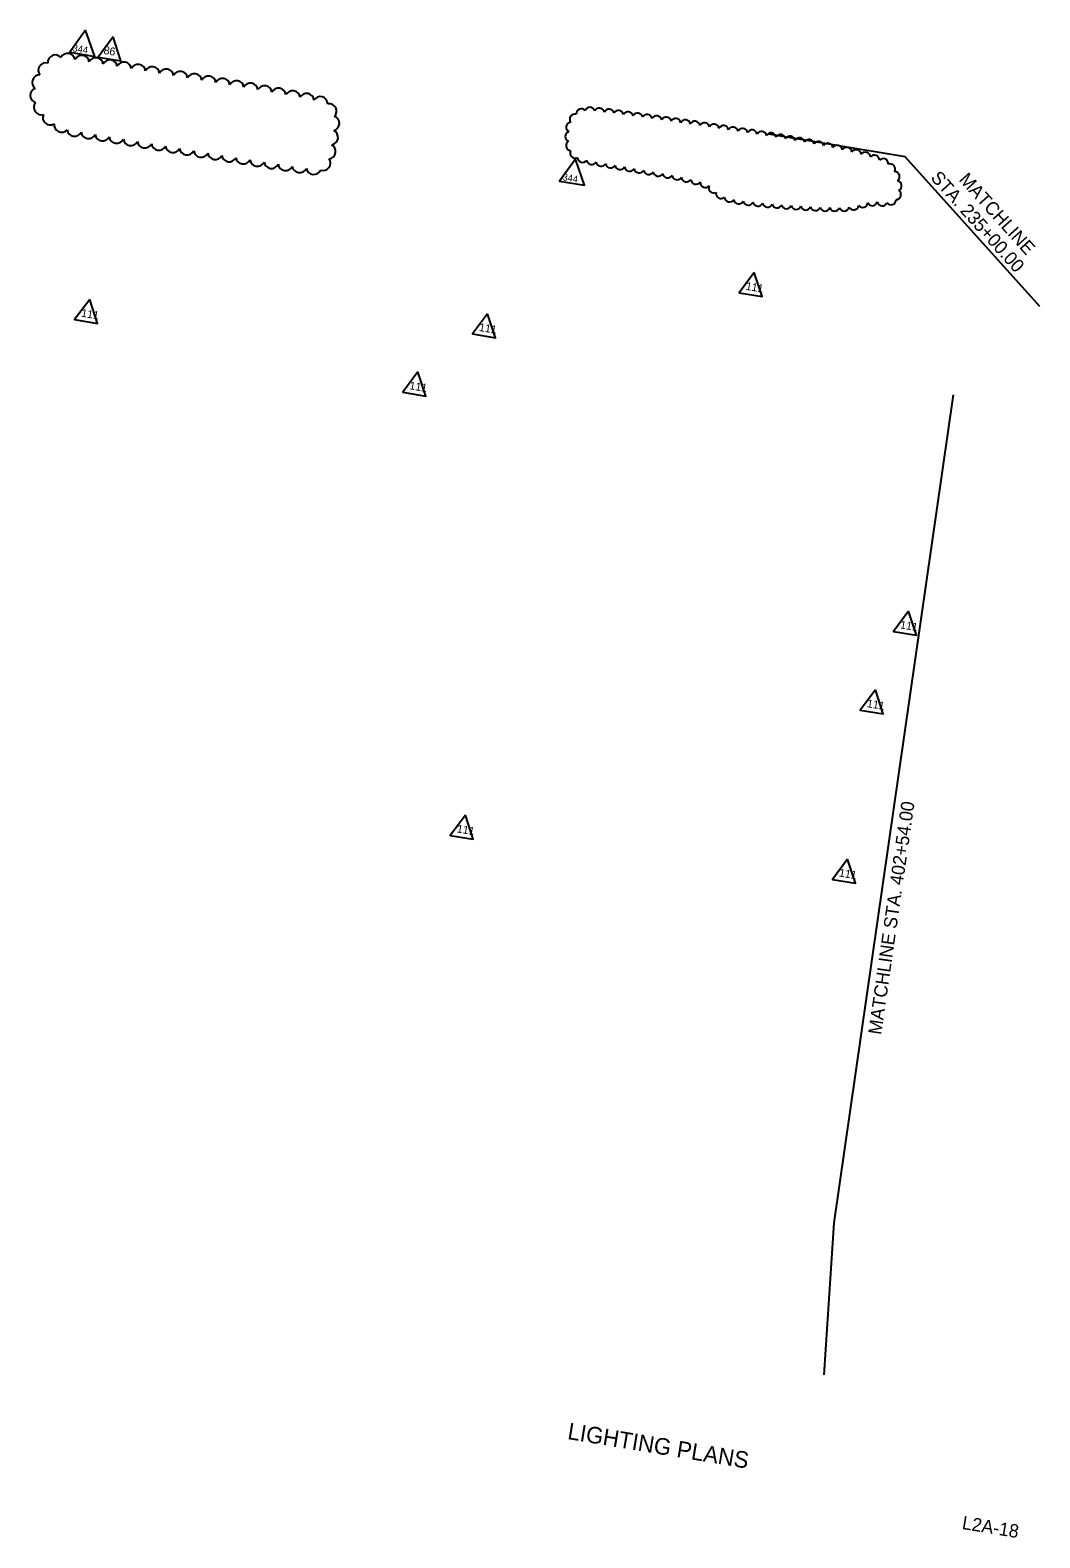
# Model space of a CAD drawing. Extents: x 927483 to 928746, y 636242 to 637203.
# Drawn here: x 928134 to 928746, y 636242 to 637154 of the extents above; entities that cross this region are included whole.
import ezdxf

# ---------------------------------------------------------------- set-up
doc = ezdxf.new("R2010")
doc.units = 0
for name, color, linetype in [('Cloud_dp', 7, 'Continuous'), ('PlotBorder_dp', 7, 'Continuous'), ('TextMisc', 7, 'Continuous'), ('TextShtNo', 7, 'Continuous')]:
    doc.layers.add(name, color=color, linetype=linetype)

msp = doc.modelspace()

# ---------------------------------------------------------------- linework, layer by layer
at = {"layer": 'Cloud_dp'}
for points in [[(928168.06, 637154.17), (928158.42, 637140.83), (928173.54, 637138.32)], [(928184.68, 637150.12), (928175.53, 637137.88), (928189.42, 637135.59)], [(928464.59, 637076.11), (928454.96, 637062.76), (928470.08, 637060.26)], [(928572.74, 637007.49), (928563.59, 636995.25), (928577.49, 636992.96)], [(928170.49, 636991.25), (928161.34, 636979.01), (928175.23, 636976.72)], [(928411.3, 636982.56), (928402.15, 636970.32), (928416.04, 636968.03)], [(928369.2, 636947.28), (928360.04, 636935.05), (928373.94, 636932.75)], [(928666.19, 636802.56), (928657.04, 636790.32), (928670.93, 636788.03)], [(928646.1, 636754.9), (928636.94, 636742.66), (928650.84, 636740.37)], [(928397.88, 636679.08), (928388.73, 636666.84), (928402.63, 636664.55)], [(928629.2, 636652.42), (928620.05, 636640.18), (928633.94, 636637.89)]]:
    msp.add_lwpolyline(points, close=True, dxfattribs=at)
for centre, radius, start, end in [((928143.89, 637129.9), 4.52, 73.90987, 218.90987), ((928149.65, 637134.66), 4.52, 40.26243, 185.26243), ((928157.18, 637135.62), 4.52, 9.30458, 154.30458), ((928165.7, 637134.35), 4.52, 8.73218, 153.73218), ((928174.22, 637133.02), 4.52, 8.52219, 153.52219), ((928182.74, 637131.66), 4.52, 8.40298, 153.40298), ((928191.26, 637130.29), 4.52, 8.32347, 153.32347), ((928199.77, 637128.91), 4.52, 8.26555, 153.26555), ((928140.25, 637122.53), 4.52, 88.47694, 233.47694), ((928208.29, 637127.52), 4.52, 8.22093, 153.22093), ((928216.8, 637126.13), 4.52, 8.18518, 153.18518), ((928225.32, 637124.73), 4.52, 8.15571, 153.15571), ((928233.83, 637123.33), 4.52, 8.11336, 153.11336), ((928242.34, 637121.92), 4.52, 8.03146, 153.03146), ((928250.85, 637120.49), 4.52, 7.9329, 152.9329), ((928259.35, 637119.05), 4.52, 7.81266, 152.81266), ((928138.99, 637114.6), 4.52, 108.37643, 253.37643), ((928267.85, 637117.58), 4.52, 7.6614, 152.6614), ((928276.35, 637116.1), 4.52, 7.46294, 152.46294), ((928284.83, 637114.57), 4.52, 7.18599, 152.18599), ((928293.31, 637113), 4.52, 6.75925, 151.75925), ((928301.75, 637111.33), 4.52, 5.9631, 150.9631), ((928141.21, 637107.42), 4.52, 141.03927, 286.03927), ((928310.1, 637109.41), 4.53, 3.089, 148.089), ((928315.41, 637105.2), 4.52, 315.06597, 100.06597), ((928468.08, 637103.53), 3.06, 40.63294, 185.63294), ((928473.28, 637104.46), 3.06, 14.7979, 159.7979), ((928479.03, 637104), 3.06, 11.05429, 156.05429), ((928484.81, 637103.31), 3.06, 10.33145, 155.33145), ((928490.6, 637102.57), 3.06, 9.95906, 154.95906), ((928146.62, 637101.29), 4.52, 156.76094, 301.76094), ((928153.48, 637096.85), 4.52, 172.43776, 317.43776), ((928317.11, 637097.74), 4.52, 285.69264, 70.69264), ((928461.97, 637095.41), 3.06, 95.38603, 240.38603), ((928464.11, 637100.31), 3.06, 72.42003, 217.42003), ((928496.38, 637101.79), 3.06, 9.72161, 154.72161), ((928502.16, 637100.99), 3.06, 9.55316, 154.55316), ((928507.93, 637100.18), 3.06, 9.42562, 154.42562), ((928513.71, 637099.35), 3.06, 9.32472, 154.32472), ((928519.48, 637098.52), 3.06, 9.24229, 154.24229), ((928525.26, 637097.68), 3.06, 9.17332, 154.17332), ((928531.03, 637096.83), 3.06, 9.11448, 154.11448), ((928536.8, 637095.98), 3.06, 9.06353, 154.06353), ((928542.57, 637095.12), 3.06, 9.01883, 154.01883), ((928548.35, 637094.26), 3.06, 8.97922, 153.97922), ((928554.12, 637093.39), 3.06, 8.94378, 153.94378), ((928161.29, 637094.43), 4.52, 188.13813, 333.13813), ((928169.81, 637093.03), 4.52, 188.13813, 333.13813), ((928178.32, 637091.62), 4.52, 188.13813, 333.13813), ((928186.83, 637090.22), 4.52, 188.13813, 333.13813), ((928195.35, 637088.82), 4.52, 188.13813, 333.13813), ((928316.33, 637089.33), 4.52, 278.78201, 63.78201), ((928461.35, 637089.82), 3.06, 106.81284, 251.81284), ((928559.89, 637092.52), 3.06, 8.91184, 153.91184), ((928565.66, 637091.65), 3.06, 8.83856, 153.83856), ((928571.42, 637090.76), 3.06, 8.65118, 153.65118), ((928577.18, 637089.85), 3.06, 8.4393, 153.4393), ((928582.94, 637088.92), 3.06, 8.20357, 153.20357), ((928588.69, 637087.96), 3.06, 7.93917, 152.93917), ((928594.44, 637086.98), 3.06, 7.63978, 152.63978), ((928600.18, 637085.96), 3.06, 7.29698, 152.29698), ((928605.92, 637084.91), 3.06, 6.89918, 151.89918), ((928203.86, 637087.41), 4.52, 188.13813, 333.13813), ((928212.37, 637086.01), 4.52, 188.13813, 333.13813), ((928220.89, 637084.6), 4.52, 188.13813, 333.13813), ((928229.4, 637083.2), 4.52, 188.13813, 333.13813), ((928237.92, 637081.8), 4.52, 188.15136, 333.15136), ((928246.43, 637080.4), 4.52, 188.21878, 333.21878), ((928254.94, 637079.02), 4.52, 188.30566, 333.30566), ((928314.89, 637080.87), 4.52, 276.84023, 61.84023), ((928461.9, 637084.25), 3.06, 119.56995, 264.56995), ((928464.31, 637079.77), 3.06, 151.98053, 296.98053), ((928611.64, 637083.82), 3.06, 6.42994, 151.42994), ((928617.35, 637082.67), 3.06, 5.86508, 150.86508), ((928623.05, 637081.46), 3.06, 5.16711, 150.16711), ((928628.73, 637080.17), 3.06, 4.27426, 149.27426), ((928634.38, 637078.78), 3.06, 3.07552, 148.07552), ((928639.98, 637077.25), 3.06, 1.34531, 146.34531), ((928645.5, 637075.5), 3.06, 358.52699, 143.52699), ((928263.46, 637077.65), 4.52, 188.41403, 333.41403), ((928271.98, 637076.3), 4.52, 188.55453, 333.55453), ((928280.5, 637074.97), 4.52, 188.74713, 333.74713), ((928289.03, 637073.68), 4.52, 189.03514, 334.03514), ((928297.55, 637072.45), 4.52, 189.53975, 334.53975), ((928306.08, 637071.36), 4.52, 190.88635, 335.88635), ((928311.74, 637073.77), 4.52, 250.27296, 35.27296), ((928468.76, 637077.2), 3.06, 182.93135, 327.93135), ((928474.39, 637075.91), 3.06, 186.32628, 331.32628), ((928480.11, 637074.82), 3.06, 187.09289, 332.09289), ((928485.85, 637073.79), 3.06, 187.49423, 332.49423), ((928491.59, 637072.79), 3.06, 187.75195, 332.75195), ((928497.34, 637071.81), 3.06, 187.93551, 332.93551), ((928503.1, 637070.85), 3.06, 188.07485, 333.07485), ((928508.85, 637069.88), 3.06, 187.92729, 332.92729), ((928650.82, 637073.36), 3.06, 352.63382, 137.63382), ((928655.04, 637070.15), 3.06, 327.95541, 112.95541), ((928514.61, 637068.88), 3.06, 187.39782, 332.39782), ((928520.36, 637067.82), 3.06, 186.70849, 331.70849), ((928526.1, 637066.68), 3.06, 185.75933, 330.75933), ((928531.82, 637065.42), 3.06, 184.33108, 329.33108), ((928537.51, 637063.95), 3.06, 181.80541, 326.80541), ((928543.12, 637062.01), 3.06, 175.00091, 320.00091), ((928548.19, 637058.65), 3.06, 152.86429, 297.86429), ((928657.66, 637065.47), 3.06, 305.50897, 90.50897), ((928658.91, 637059.97), 3.06, 294.95743, 79.95743), ((928552.61, 637055.32), 3.06, 168.26885, 313.26885), ((928557.77, 637053.23), 3.06, 182.59517, 327.59517), ((928563.37, 637052.07), 3.06, 188.97993, 333.97993), ((928569.13, 637051.3), 3.06, 190.78991, 335.78991), ((928655.51, 637051.51), 3.06, 216.51399, 1.51399), ((928658.5, 637054.65), 3.06, 271.24021, 56.24021), ((928574.91, 637050.67), 3.06, 191.72761, 336.72761), ((928580.71, 637050.11), 3.06, 192.32661, 337.32661), ((928586.52, 637049.61), 3.06, 192.75186, 337.75186), ((928592.33, 637049.14), 3.06, 193.07393, 338.07393), ((928598.15, 637048.71), 3.06, 193.3964, 338.3964), ((928603.96, 637048.32), 3.06, 193.9412, 338.9412), ((928609.78, 637047.99), 3.06, 194.66476, 339.66476), ((928615.59, 637047.76), 3.06, 195.66832, 340.66832), ((928621.4, 637047.65), 3.06, 197.19682, 342.19682), ((928627.19, 637047.76), 3.06, 199.96678, 344.96678), ((928632.84, 637048.41), 3.06, 208.14735, 353.14735), ((928638.35, 637049.86), 3.06, 216.33537, 1.33537), ((928644.28, 637050.98), 3.06, 200.14494, 345.14494), ((928650.22, 637050.86), 3.06, 192.51704, 337.51704)]:
    msp.add_arc(centre, radius, start, end, dxfattribs=at)
at = {"layer": 'PlotBorder_dp'}
for p, q in [((928664.04, 637077.53), (928581.41, 637091.16)), ((928745.61, 636986.83), (928664.04, 637077.53)), ((928693.09, 636933.47), (928620.98, 636432.26)), ((928620.98, 636432.26), (928614.87, 636340.32))]:
    msp.add_line(p, q, dxfattribs=at)

# ---------------------------------------------------------------- texts
at = {"layer": 'Cloud_dp'}
for s, height, p in [('344', 4.2, (928159.87, 637141.44)), ('86', 4.8, (928178.66, 637139.81)), ('344', 4.2, (928456.41, 637063.37)), ('111', 4.8, (928567.35, 636997.07)), ('111', 4.8, (928165.09, 636980.83)), ('111', 4.8, (928405.9, 636972.15)), ('111', 4.8, (928363.8, 636936.87)), ('111', 4.8, (928660.79, 636792.15)), ('111', 4.8, (928640.7, 636744.49)), ('111', 4.8, (928392.49, 636668.67)), ('111', 4.8, (928623.8, 636642.01))]:
    msp.add_text(s, height=height, rotation=350.63813, dxfattribs=at).set_placement(p)
at = {"layer": 'PlotBorder_dp'}
for s, rotation, p in [('STA. 235+00.00', 311.9666, (928679.06, 637064.5)), ('MATCHLINE', 311.9666, (928696.2, 637063.39)), ('MATCHLINE STA. 402+54.00', 81.81299, (928649.58, 636545.86))]:
    msp.add_text(s, height=8, rotation=rotation, dxfattribs=at).set_placement(p)
at = {"layer": 'TextMisc'}
msp.add_text('        LIGHTING PLANS         ', height=10, rotation=350.63813, dxfattribs=at).set_placement((928429.98, 636306.38))
at = {"layer": 'TextShtNo'}
msp.add_text('L2A-18', height=8, rotation=350.63813, dxfattribs=at).set_placement((928698.13, 636247.11))

doc.saveas('drawing.dxf')
